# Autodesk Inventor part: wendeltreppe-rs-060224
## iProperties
Created: 2006-02
Part Number: wendeltreppe-rs-060224
Cost Center: 0 kg
Document SubType Name: Modeling
Designer: rsc
Authority: 0 mm^3
Author: rsc
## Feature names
1. Extrusion1
2. Spirale1
3. Extrusion2
4. Rechteckige Anordnung1 [Rectangular Pattern]
5. Extrusion3
